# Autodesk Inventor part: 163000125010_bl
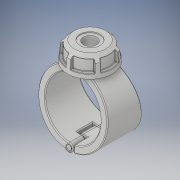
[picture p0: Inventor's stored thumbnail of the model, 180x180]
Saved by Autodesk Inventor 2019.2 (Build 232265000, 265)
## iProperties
Created: 2022-02
Part Number: 163000125010_bl
Material: Generic
Description: Plassadle Threaded 125x1''
Document SubType Name: Modeling
Designer: comp2
Density: 1 g/cm^3
Appearance: Default
Author: comp2
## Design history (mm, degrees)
derived "16300.ipt"
feature "Solid1::16300.ipt" dims "ScaleForDerivedMember" = 10
feature "Solid2::16300.ipt" dims "ScaleForDerivedMember" = 10
feature "Solid3::16300.ipt" dims "ScaleForDerivedMember" = 10
feature "Solid4::16300.ipt" dims "ScaleForDerivedMember" = 10
tag "TaggingFeature1"
body "Solid1"
body "Solid2"
body "Solid3"
body "Solid4"
other parameters: "d0" = 125 [user parameter], "d2" = 157 [user parameter], "d3" = 62.5 [user parameter], "d7" = 149.15 [user parameter], "d8" = 85 deg [user parameter], "d9" = 45 deg [user parameter], "d10" = 102 [user parameter], "d11" = 49 [user parameter], "d12" = 29.2495 [user parameter], "d13" = 42.84 [user parameter], "d14" = 45.4365 [user parameter], "d42" = 3.2 [user parameter], "d49" = 3.14 [user parameter], "d51" = 0 [user parameter], "d52" = 22.4 [user parameter], "d53" = 86.35 [user parameter], "d54" = 35 [user parameter], "d55" = 0 [user parameter], "d59" = 0 [user parameter], "d61" = 0 [user parameter], "d62" = 35 [user parameter], "d63" = 0 [user parameter], "d65" = 0 [user parameter], "d67" = 0 [user parameter], "d69" = 0 [user parameter], "d70" = 1 [user parameter], "d71" = 96 [user parameter], "d72" = 0 [user parameter], "d73" = 2 [user parameter], "d78" = 86.7 [user parameter], "d79" = 5.1 [user parameter], "d80" = 60 deg [user parameter], "d81" = 5.1 [user parameter], "d84" = 0 [user parameter], "d85" = 1 [user parameter], "d87" = 360 deg [user parameter], "d122" = 49 [user parameter], "d124" = 42.80128 [user parameter], "d125" = 2.08925 [user parameter], "d127" = 198 [user parameter], "d129" = 30.291 [user parameter], "d130" = 25.74735 [user parameter], "d131" = 31.85 [user parameter], "d132" = 45 deg [user parameter], "d133" = 22.295 [user parameter], "d134" = 15.1455 [user parameter], "d136" = 0 [user parameter], "d138" = 0 [user parameter], "d" = 125 [user parameter], "d1" = 25 [user parameter], "B" = 157 [user parameter], "E_" = 54 [user parameter], "E1" = 102 [user parameter], "H1" = 198 [user parameter], "H2" = 49 [user parameter], "H3" = 78 [user parameter], "H_costum" = 49 [user parameter], "Rp" = 30.291 [user parameter], "d128" = 41.785 [user parameter]
